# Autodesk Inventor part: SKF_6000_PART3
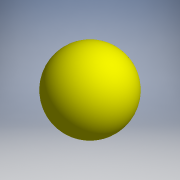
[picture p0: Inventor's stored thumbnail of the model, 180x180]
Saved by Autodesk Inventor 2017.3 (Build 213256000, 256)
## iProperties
Part Number: SKF_6000_PART3
Material: Generic
Catalog Web Link: www.cadenas.de
Description: -Deep groove ball bearings
Vendor: SKF
Document SubType Name: Modeling
Designer: partserver
Manufacturer: SKF
Mass: 19 g
Surface Area: 0.712408 cm^2
Volume: 0.0565414 cm^3
Density: 1 g/cm^3
Appearance: PSOLRGB-192-192-192
Category: PARTsolutions
Company: SKF
Title: SKF_6000_PART3
Author: Cadenas PARTsolutions
Comments: Deep groove ball bearings
PSOL_IDENT_0: {$CADENAS_DATA\23d-libs\skf\bearings_units_and_housings\ball_bearings\deep_groove_ball_bearings\bb1_
PSOL_IDENT_1: 001_101.prj},194 {VTYP=3D},{NB=SKF_6000_PART3},{LINA=SKF_6000_PART3},{NN=BB1_001_101_PART3},{NOPRJ=T
PSOL_IDENT_2: RUE},{DATE=18.06.2021 07:30:58},{GEOMDATE=16.06.2021 12:48:44},{VERSION=},{LINEID=5840},{WBVAR=},{WB
PSOL_IDENT_3: NUMERIC=}  {NB=SKF_6000_PART3},{LINA=SKF_6000_PART3},{KT=DUMMY},{DESIGNATION=6000},{R12=0.30},{DD=10
PSOL_IDENT_4: .000},{D=26.000},{B=8.000},{C=},{CX=},{CXX=},{CA=0.000},{XXVARIANT=},{XXDESIGN=Single row},{XXSEALIN
PSOL_IDENT_5: G=No seals},{DESIGN=dgbb1},{DESIGNIR=dgbb1},{VARIANT=},{DD1=14.80},{DD2=},{DD2X=},{DD2A=0.00},{D1=21
PSOL_IDENT_6: .20},{D1X=MIN},{D2=22.6},{D2A=22.60},{D3=},{D3X=},{D3A=0.000},{D4=},{HH=MIN},{BB=MIN},{BBX=},{BBA=0.
PSOL_IDENT_7: 000},{FF=},{R0MAX=MIN},{R0=MIN},{PITCH=17.80},{DW=4.762},{DDAMIN=12.000},{DDAMAX=MIN},{DDBMIN=MIN},{
PSOL_IDENT_8: DDBMAX=MIN},{DBMIN=MIN},{DAMAX=24.000},{BBAMIN=MIN},{CAMAX=MIN},{RAMAX=0.300},{LOAD1=4.750},{LOAD2=1
PSOL_IDENT_9: .960},{LOAD3=0.083},{SPEED1=67000},{SPEED2=40000},{KR=0.025},{F0=12.000},{Z=7},{II=1},{MASS=0.019},{
PSOL_IDENT_10: BEARING=6000},{RING=},{HELP=2.400},{HELP2=1.700},{DD1ALG=7.400},{YALG=7.400},{PITCH1=17.800},{DW1=4.
PSOL_IDENT_11: 762},{YALG1=10.600},{HALG1=2.400},{SH=7.400},{CU=0.648},{HALG=2.4},{B1=0},{SHIELDHELP=1},{D4A=0.000}
PSOL_IDENT_12: ,{FFA=0.000},{RS1=}
NB: SKF_6000_PART3
NT: Deep groove ball bearings
NBSYN: SKF_$DESIGNATION._PART3
LINA: SKF_6000_PART3
CATALOG: SKF
DESIGNATION: 6000
R12: 0.3
DD: 10
D: 26
B: 8
D2: 22.6
LOAD1: 4.75
LOAD2: 1.96
LOAD3: 0.083
SPEED1: 67000
SPEED2: 40000
BEARING: 6000
SUPPLIER: SKF
ARTICLENO: SKF_6000_PART3
BOMINFO: SKF_6000_PART3
CREATOR: CADENAS GmbH
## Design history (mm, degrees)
sketch "Sketch_6"
  geometry: L1 (6.381, 8.9)-(1.619, 8.9); L2 (6.381, 8.9)-(1.619, 8.9); A1 r 2.381 centre (4, 8.9) between (6.381, 8.9) and (1.619, 8.9)
  constraints: 4 end point, 2 point on circle, 1 centre point
  dimensions: "d0" = 360 deg dimension on L1.start L1.end L1 L2.end L2.start A1.centre A1 L2
revolve "Revolution1" sketch "Sketch_6" stored, may be unused: angle "d0" = 360 deg
body "Solid1"
